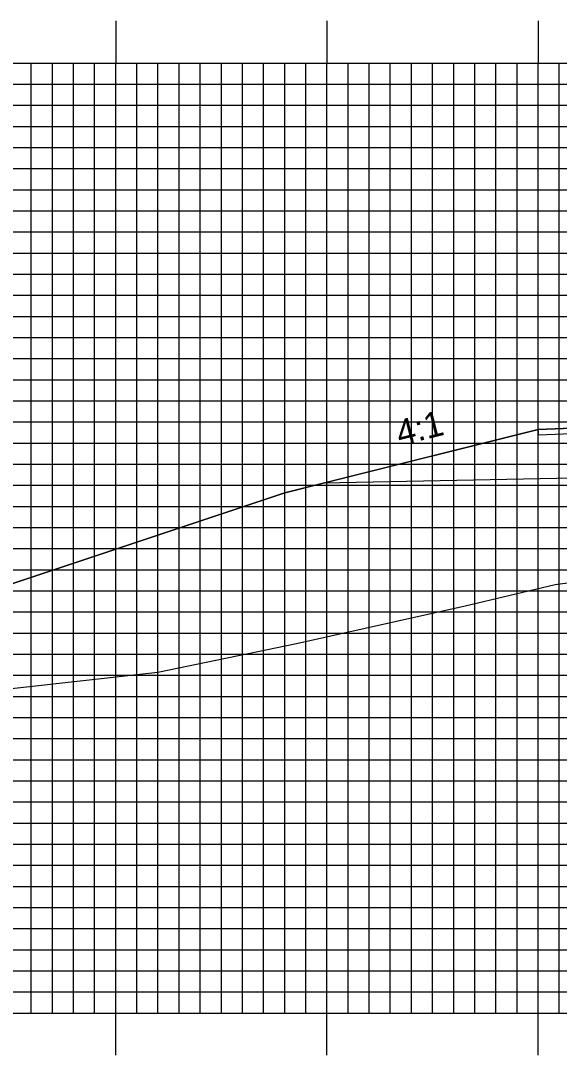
# Model space of a CAD drawing. Extents: x 1782254 to 1782597, y 442591 to 442811.
# Drawn here: x 1782374.93 to 1782400.43, y 442716.66 to 442765.67 of the extents above; entities that cross this region are included whole.
import ezdxf

# ---------------------------------------------------------------- set-up
doc = ezdxf.new("R2010")
doc.units = 0
for name, color, linetype in [('ANNOTATION', 7, 'Continuous'), ('D_Roadway_Centerline', 7, 'Continuous'), ('D_Roadway_Edge_Shoulder', 7, 'Continuous'), ('D_Roadway_SlopeLines', 7, 'Continuous'), ('D_Roadway_SubGrade', 7, 'Continuous'), ('MAJOR', 7, 'Continuous'), ('MINOR', 7, 'Continuous'), ('S_Roadway_Centerline', 7, 'Continuous')]:
    doc.layers.add(name, color=color, linetype=linetype)

msp = doc.modelspace()

# ---------------------------------------------------------------- linework, layer by layer
at = {"layer": 'D_Roadway_Centerline'}
msp.add_lwpolyline([(1782351.984, 442731.486), (1782387.434, 442743.303), (1782389.26, 442743.759), (1782399.434, 442746.303), (1782407.434, 442746.623), (1782419.434, 442746.863), (1782431.434, 442746.623), (1782439.434, 442746.303), (1782449.608, 442743.759), (1782453.608, 442742.759), (1782457.483, 442744.696), (1782458.733, 442745.255), (1782459.983, 442745.682), (1782461.233, 442745.977), (1782462.483, 442746.14)], dxfattribs=at)
at = {"layer": 'D_Roadway_Edge_Shoulder'}
msp.add_lwpolyline([(1782407.434, 442746.623), (1782399.434, 442746.303), (1782399.434, 442746.053), (1782407.434, 442746.373)], close=True, dxfattribs=at)
at = {"layer": 'D_Roadway_SlopeLines'}
msp.add_lwpolyline([(1782399.434, 442746.303), (1782387.434, 442743.303), (1782351.984, 442731.486)], dxfattribs=at)
at = {"layer": 'D_Roadway_SubGrade'}
msp.add_lwpolyline([(1782407.434, 442744.123), (1782389.26, 442743.759), (1782399.434, 442746.303), (1782399.434, 442746.053), (1782407.434, 442746.373), (1782419.434, 442746.613), (1782431.434, 442746.373), (1782439.434, 442746.053), (1782439.434, 442746.303), (1782449.608, 442743.759), (1782431.434, 442744.123), (1782419.434, 442744.363)], close=True, dxfattribs=at)
at = {"layer": 'MAJOR'}
for p, q in [((1782379.434, 442765.669), (1782379.434, 442763.665)), ((1782389.434, 442765.669), (1782389.434, 442763.665)), ((1782399.434, 442765.669), (1782399.434, 442763.665)), ((1782279.434, 442763.665), (1782559.434, 442763.665)), ((1782279.434, 442763.665), (1782559.434, 442763.665)), ((1782379.434, 442718.665), (1782379.434, 442763.665)), ((1782389.434, 442718.665), (1782389.434, 442763.665)), ((1782399.434, 442718.665), (1782399.434, 442763.665)), ((1782279.434, 442758.665), (1782559.434, 442758.665)), ((1782279.434, 442753.665), (1782559.434, 442753.665)), ((1782279.434, 442748.665), (1782559.434, 442748.665)), ((1782279.434, 442743.665), (1782559.434, 442743.665)), ((1782279.434, 442738.665), (1782559.434, 442738.665)), ((1782279.434, 442733.665), (1782559.434, 442733.665)), ((1782279.434, 442728.665), (1782559.434, 442728.665)), ((1782279.434, 442723.665), (1782559.434, 442723.665)), ((1782279.434, 442718.665), (1782559.434, 442718.665)), ((1782279.434, 442718.665), (1782559.434, 442718.665)), ((1782379.434, 442716.661), (1782379.434, 442718.665)), ((1782389.434, 442716.661), (1782389.434, 442718.665)), ((1782399.434, 442716.661), (1782399.434, 442718.665))]:
    msp.add_line(p, q, dxfattribs=at)
at = {"layer": 'MINOR'}
for p, q in [((1782375.434, 442718.665), (1782375.434, 442763.665)), ((1782376.434, 442718.665), (1782376.434, 442763.665)), ((1782377.434, 442718.665), (1782377.434, 442763.665)), ((1782378.434, 442718.665), (1782378.434, 442763.665)), ((1782380.434, 442718.665), (1782380.434, 442763.665)), ((1782381.434, 442718.665), (1782381.434, 442763.665)), ((1782382.434, 442718.665), (1782382.434, 442763.665)), ((1782383.434, 442718.665), (1782383.434, 442763.665)), ((1782384.434, 442718.665), (1782384.434, 442763.665)), ((1782385.434, 442718.665), (1782385.434, 442763.665)), ((1782386.434, 442718.665), (1782386.434, 442763.665)), ((1782387.434, 442718.665), (1782387.434, 442763.665)), ((1782388.434, 442718.665), (1782388.434, 442763.665)), ((1782390.434, 442718.665), (1782390.434, 442763.665)), ((1782391.434, 442718.665), (1782391.434, 442763.665)), ((1782392.434, 442718.665), (1782392.434, 442763.665)), ((1782393.434, 442718.665), (1782393.434, 442763.665)), ((1782394.434, 442718.665), (1782394.434, 442763.665)), ((1782395.434, 442718.665), (1782395.434, 442763.665)), ((1782396.434, 442718.665), (1782396.434, 442763.665)), ((1782397.434, 442718.665), (1782397.434, 442763.665)), ((1782398.434, 442718.665), (1782398.434, 442763.665)), ((1782400.434, 442718.665), (1782400.434, 442763.665)), ((1782279.434, 442762.665), (1782559.434, 442762.665)), ((1782279.434, 442761.665), (1782559.434, 442761.665)), ((1782279.434, 442760.665), (1782559.434, 442760.665)), ((1782279.434, 442759.665), (1782559.434, 442759.665)), ((1782279.434, 442757.665), (1782559.434, 442757.665)), ((1782279.434, 442756.665), (1782559.434, 442756.665)), ((1782279.434, 442755.665), (1782559.434, 442755.665)), ((1782279.434, 442754.665), (1782559.434, 442754.665)), ((1782279.434, 442752.665), (1782559.434, 442752.665)), ((1782279.434, 442751.665), (1782559.434, 442751.665)), ((1782279.434, 442750.665), (1782559.434, 442750.665)), ((1782279.434, 442749.665), (1782559.434, 442749.665)), ((1782279.434, 442747.665), (1782559.434, 442747.665)), ((1782279.434, 442746.665), (1782559.434, 442746.665)), ((1782279.434, 442745.665), (1782559.434, 442745.665)), ((1782279.434, 442744.665), (1782559.434, 442744.665)), ((1782279.434, 442742.665), (1782559.434, 442742.665)), ((1782279.434, 442741.665), (1782559.434, 442741.665)), ((1782279.434, 442740.665), (1782559.434, 442740.665)), ((1782279.434, 442739.665), (1782559.434, 442739.665)), ((1782279.434, 442737.665), (1782559.434, 442737.665)), ((1782279.434, 442736.665), (1782559.434, 442736.665)), ((1782279.434, 442735.665), (1782559.434, 442735.665)), ((1782279.434, 442734.665), (1782559.434, 442734.665)), ((1782279.434, 442732.665), (1782559.434, 442732.665)), ((1782279.434, 442731.665), (1782559.434, 442731.665)), ((1782279.434, 442730.665), (1782559.434, 442730.665)), ((1782279.434, 442729.665), (1782559.434, 442729.665)), ((1782279.434, 442727.665), (1782559.434, 442727.665)), ((1782279.434, 442726.665), (1782559.434, 442726.665)), ((1782279.434, 442725.665), (1782559.434, 442725.665)), ((1782279.434, 442724.665), (1782559.434, 442724.665)), ((1782279.434, 442722.665), (1782559.434, 442722.665)), ((1782279.434, 442721.665), (1782559.434, 442721.665)), ((1782279.434, 442720.665), (1782559.434, 442720.665)), ((1782279.434, 442719.665), (1782559.434, 442719.665))]:
    msp.add_line(p, q, dxfattribs=at)
at = {"layer": 'S_Roadway_Centerline'}
msp.add_lwpolyline([(1782346.891, 442731.172), (1782359.715, 442731.963), (1782365.175, 442733.019), (1782371.508, 442733.698), (1782381.434, 442734.81), (1782387.999, 442736.171), (1782395.979, 442737.945), (1782400.231, 442738.955), (1782404.003, 442739.472), (1782418.802, 442741.297), (1782427.054, 442742.71), (1782434.028, 442743.696), (1782441.593, 442744.334), (1782446.036, 442744.805), (1782450.006, 442745.176), (1782466.168, 442746.424), (1782469.44, 442746.736), (1782472.854, 442747.043)], dxfattribs=at)

# ---------------------------------------------------------------- texts
at = {"layer": 'ANNOTATION'}
msp.add_text('4:1', height=1.2, rotation=14.0362, dxfattribs=at).set_placement((1782392.883, 442745.526))

doc.saveas('drawing.dxf')
